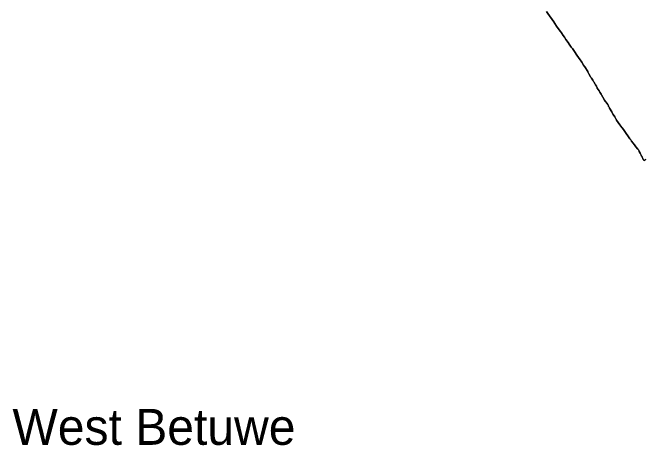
# Model space of a CAD drawing. Extents: x 113371 to 291721, y 393993 to 520143.
# Drawn here: x 139834 to 148639, y 430680 to 436701 of the extents above; entities that cross this region are included whole.
import ezdxf

# ---------------------------------------------------------------- set-up
doc = ezdxf.new("R2010")
doc.units = 0
doc.layers.add('Default', color=7, linetype='Continuous')
doc.layers.add('plaatsnamen', color=7, linetype='Continuous')

msp = doc.modelspace()

# ---------------------------------------------------------------- linework, layer by layer
at = {"layer": 'Default'}
for points in [[(147263.785625, 436717.9825), (147283.795625, 436689.4725), (147365.825625, 436570.6525), (147381.185625, 436548.5725), (147404.655625, 436514.8525)], [(147365.825625, 436570.6525), (147283.795625, 436689.4725), (147263.785625, 436717.9825)], [(147957.285625, 435677.4525), (147945.605625, 435698.4025), (147941.485625, 435705.9425), (147919.895625, 435737.6025), (147917.905625, 435740.8825), (147906.365625, 435759.8725), (147896.895625, 435775.5125), (147888.125625, 435789.9825), (147885.475625, 435794.5425), (147881.195625, 435801.7525), (147877.765625, 435809.2825), (147852.405625, 435850.6225), (147843.075625, 435867.3025), (147840.715625, 435871.5325), (147840.695625, 435871.5725), (147838.145625, 435880.2725), (147798.565625, 435945.4925), (147797.015625, 435946.9625), (147792.645625, 435951.0925), (147780.685625, 435971.0425), (147753.535625, 436012.3225), (147745.425625, 436024.1225), (147731.515625, 436044.3625), (147684.935625, 436111.2925), (147651.625625, 436158.9925), (147623.385625, 436199.9925), (147607.575625, 436222.6125), (147581.085625, 436260.6725), (147563.335625, 436285.9925), (147534.425625, 436327.8325), (147512.345625, 436359.5825), (147496.995625, 436382.1025), (147472.245625, 436417.5425), (147457.995625, 436438.1925), (147440.325625, 436463.5925), (147404.655625, 436514.8525), (147381.185625, 436548.5725), (147365.825625, 436570.6525)], [(147404.655625, 436514.8525), (147440.325625, 436463.5925), (147457.995625, 436438.1925), (147472.245625, 436417.5425), (147496.995625, 436382.1025), (147512.345625, 436359.5825), (147534.425625, 436327.8325), (147563.335625, 436285.9925), (147581.085625, 436260.6725), (147607.575625, 436222.6125), (147623.385625, 436199.9925), (147651.625625, 436158.9925), (147684.935625, 436111.2925), (147731.515625, 436044.3625), (147745.425625, 436024.1225), (147753.535625, 436012.3225), (147780.685625, 435971.0425), (147792.645625, 435951.0925), (147797.015625, 435946.9625), (147798.565625, 435945.4925), (147838.145625, 435880.2725), (147840.695625, 435871.5725), (147840.715625, 435871.5325), (147843.075625, 435867.3025), (147852.405625, 435850.6225), (147877.765625, 435809.2825), (147881.195625, 435801.7525), (147885.475625, 435794.5425), (147888.125625, 435789.9825), (147896.895625, 435775.5125), (147906.365625, 435759.8725), (147917.905625, 435740.8825), (147919.895625, 435737.6025), (147941.485625, 435705.9425), (147945.605625, 435698.4025), (147957.285625, 435677.4525), (147960.255625, 435672.1825), (147964.675625, 435662.8825)], [(148312.795625, 435102.6125), (148286.275625, 435139.3225), (148262.855625, 435172.1525), (148238.175625, 435206.7525), (148233.145625, 435213.9325), (148236.185625, 435214.4925), (148230.215625, 435223.5325), (148214.305625, 435249.2225), (148191.885625, 435285.5825), (148172.305625, 435317.3225), (148171.005625, 435319.5425), (148170.695625, 435320.0625), (148140.495625, 435371.2725), (148140.825625, 435372.4125), (148141.395625, 435373.3425), (148141.345625, 435373.7225), (148140.145625, 435376.1425), (148133.925625, 435386.5125), (148128.525625, 435396.5925), (148126.375625, 435401.1025), (148124.795625, 435405.2525), (148114.725625, 435421.4125), (148102.415625, 435441.9325), (148088.885625, 435458.7525), (148086.815625, 435461.3225), (148082.155625, 435468.4725), (148072.405625, 435483.8925), (148046.385625, 435525.0925), (148045.305625, 435526.8125), (148027.295625, 435556.9325), (148023.085625, 435564.0125), (148006.285625, 435592.9025), (147994.325625, 435612.3225), (147970.815625, 435652.0025), (147966.425625, 435659.1925), (147964.675625, 435662.8825), (147960.255625, 435672.1825), (147957.285625, 435677.4525)], [(147964.675625, 435662.8825), (147966.425625, 435659.1925), (147970.815625, 435652.0025), (147994.325625, 435612.3225), (148006.285625, 435592.9025), (148023.085625, 435564.0125), (148027.295625, 435556.9325), (148045.305625, 435526.8125), (148046.385625, 435525.0925), (148072.405625, 435483.8925), (148082.155625, 435468.4725), (148086.815625, 435461.3225), (148088.885625, 435458.7525), (148102.415625, 435441.9325), (148114.725625, 435421.4125), (148124.795625, 435405.2525), (148126.375625, 435401.1025), (148128.525625, 435396.5925), (148133.925625, 435386.5125), (148140.145625, 435376.1425), (148141.345625, 435373.7225), (148141.395625, 435373.3425), (148140.825625, 435372.4125), (148140.495625, 435371.2725), (148170.695625, 435320.0625), (148171.005625, 435319.5425), (148172.305625, 435317.3225), (148191.885625, 435285.5825), (148214.305625, 435249.2225), (148230.215625, 435223.5325), (148236.185625, 435214.4925), (148233.145625, 435213.9325), (148238.175625, 435206.7525), (148262.855625, 435172.1525), (148286.275625, 435139.3225), (148312.795625, 435102.6125), (148316.235625, 435097.8625), (148333.385625, 435073.6625)], [(148623.535625, 434637.6625), (148622.885625, 434638.3025), (148621.105625, 434637.6125), (148621.965625, 434642.8325), (148622.115625, 434647.3525), (148621.735625, 434649.0825), (148618.475625, 434652.5825), (148614.535625, 434655.1425), (148613.415625, 434653.8325), (148610.305625, 434657.8925), (148605.885625, 434666.0225), (148602.735625, 434672.1225), (148597.945625, 434682.1525), (148593.795625, 434690.7425), (148588.715625, 434701.4825), (148588.455625, 434701.9925), (148587.175625, 434704.4725), (148580.825625, 434716.9425), (148566.095625, 434744.5225), (148553.065625, 434768.7425), (148546.215625, 434786.2425), (148539.575625, 434794.4825), (148532.865625, 434802.8125), (148506.415625, 434835.6225), (148485.855625, 434861.9825), (148482.985625, 434865.9125), (148470.275625, 434883.3325), (148447.665625, 434914.6225), (148441.745625, 434922.7525), (148436.165625, 434930.4225), (148431.485625, 434936.8525), (148425.145625, 434945.5625), (148406.825625, 434971.1325), (148362.895625, 435031.6425), (148362.085625, 435032.8025), (148333.385625, 435073.6625), (148316.235625, 435097.8625), (148312.795625, 435102.6125)], [(148333.385625, 435073.6625), (148362.085625, 435032.8025), (148362.895625, 435031.6425), (148406.825625, 434971.1325), (148425.145625, 434945.5625), (148431.485625, 434936.8525), (148436.165625, 434930.4225), (148441.745625, 434922.7525), (148447.665625, 434914.6225), (148470.275625, 434883.3325), (148482.985625, 434865.9125), (148485.855625, 434861.9825), (148506.415625, 434835.6225), (148532.865625, 434802.8125), (148539.575625, 434794.4825), (148546.215625, 434786.2425), (148553.065625, 434768.7425), (148566.095625, 434744.5225), (148580.825625, 434716.9425), (148587.175625, 434704.4725), (148588.455625, 434701.9925), (148588.715625, 434701.4825), (148593.795625, 434690.7425), (148597.945625, 434682.1525), (148602.735625, 434672.1225), (148605.885625, 434666.0225), (148610.305625, 434657.8925), (148613.415625, 434653.8325), (148614.535625, 434655.1425), (148618.475625, 434652.5825), (148621.735625, 434649.0825), (148622.115625, 434647.3525), (148621.965625, 434642.8325), (148621.105625, 434637.6125), (148622.885625, 434638.3025), (148623.535625, 434637.6625), (148627.665625, 434642.0425), (148629.575625, 434644.4625)], [(148644.325625, 434659.2925), (148636.235625, 434651.1725), (148631.825625, 434646.7225), (148629.575625, 434644.4625), (148627.665625, 434642.0425), (148623.535625, 434637.6625)], [(148629.575625, 434644.4625), (148631.825625, 434646.7225), (148636.235625, 434651.1725), (148644.325625, 434659.2925)]]:
    msp.add_lwpolyline(points, dxfattribs=at)

# ---------------------------------------------------------------- texts
at = {"layer": 'plaatsnamen'}
msp.add_text('West Betuwe', height=500, dxfattribs=at).set_placement((139831.289465, 430686.744825))

doc.saveas('drawing.dxf')
